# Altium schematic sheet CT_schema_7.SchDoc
size 302 x 170 mm
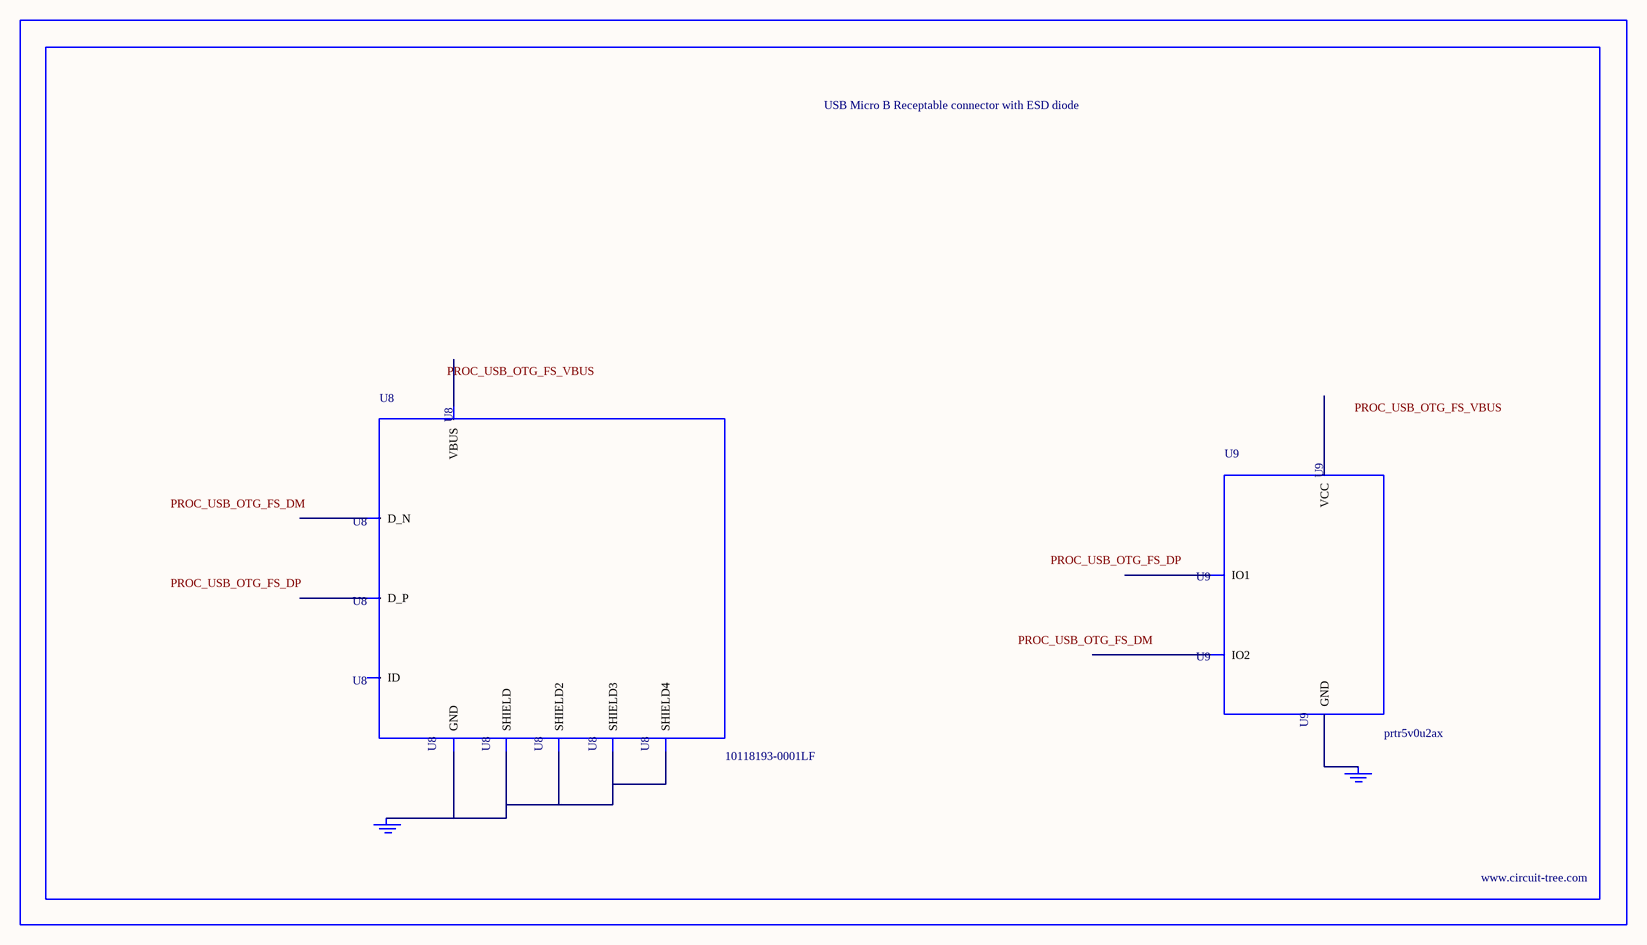
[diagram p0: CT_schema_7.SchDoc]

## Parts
BORDER6  (no value)
GND_INSTANCE_6_0  (no value)
GND_INSTANCE_6_1  (no value)
U8  10118193-0001LF  [FCI_10118193-0001LF]
U9  prtr5v0u2ax  [SOT143B]

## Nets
NetGND_INSTANCE_6_0_0: GND_INSTANCE_6_0.0(GND) U8.5(GND) U8.6(SHIELD) U8.7(SHIELD2) U8.8(SHIELD3) U8.9(SHIELD4)
NetGND_INSTANCE_6_1_0: GND_INSTANCE_6_1.0(GND) U9.1(GND)

Not connected (* = marked no-connect by the designer): U8 1(VBUS) 2(D_N) 3(D_P) 4(ID); U9 2(IO1) 3(IO2) 4(VCC)

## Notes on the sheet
- Labels drawn without touching a wire or pin: PROC_USB_OTG_FS_DM, PROC_USB_OTG_FS_DP, PROC_USB_OTG_FS_VBUS

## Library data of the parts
BORDER6 = BORDER_PAGE6
GND_INSTANCE_6_0 GND_INSTANCE_6_1 = GND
